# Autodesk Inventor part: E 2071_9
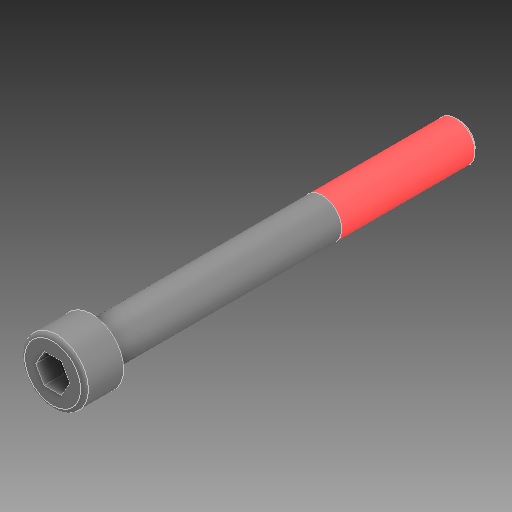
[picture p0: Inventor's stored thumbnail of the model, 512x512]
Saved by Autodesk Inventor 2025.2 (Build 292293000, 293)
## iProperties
Created: 2025-04
Part Number: E 2071_9
Material: Všeobecné
Document SubType Name: Modeling
Designer: Patrik
Density: 1 g/cm^3
Appearance: Výchozí
Mass: 4.70743 g
Surface Area: 25.3265 cm^2
Volume: 4.70743 cm^3
Author: Patrik
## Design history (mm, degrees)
feature "Base1"
node "Těleso1"
